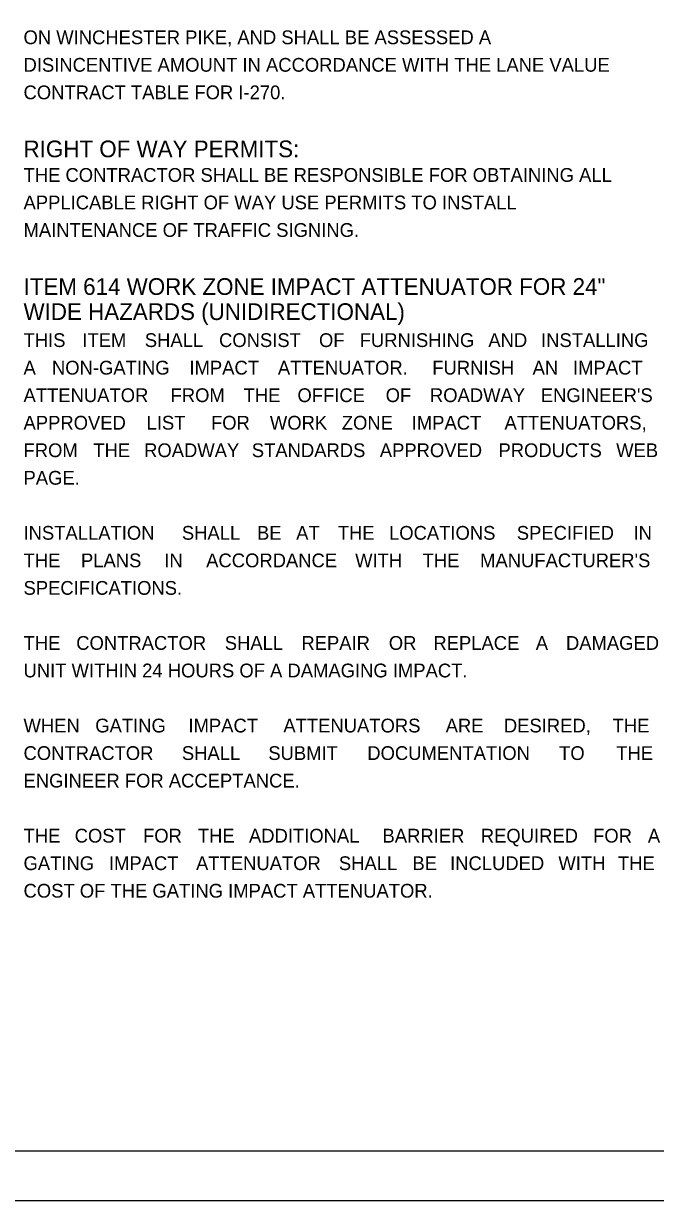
# Model space of a CAD drawing. Extents: x 0 to 34, y 0 to 22.
# Drawn here: x 17.74 to 24.17, y 0 to 11.97 of the extents above; entities that cross this region are included whole.
import ezdxf

# ---------------------------------------------------------------- set-up
doc = ezdxf.new("R2010")
doc.units = 0
for name, color, linetype in [('BD_P_Text', 7, 'Continuous'), ('SH_Border', 7, 'Continuous'), ('SH_Cut_Line', 7, 'Continuous')]:
    doc.layers.add(name, color=color, linetype=linetype)

msp = doc.modelspace()

# ---------------------------------------------------------------- linework, layer by layer
at = {"layer": 'SH_Border'}
msp.add_lwpolyline([(2, 21.5), (33.5, 21.5), (33.5, 0.5), (2, 0.5)], close=True, dxfattribs=at)
at = {"layer": 'SH_Cut_Line'}
msp.add_lwpolyline([(0, 0), (34, 0), (34, 22), (0, 22)], close=True, dxfattribs=at)

# ---------------------------------------------------------------- texts
at = {"layer": 'BD_P_Text'}
for s, height, p in [('ON WINCHESTER PIKE, AND SHALL BE ASSESSED A ', 0.14, (17.74, 11.76)), ('DISINCENTIVE AMOUNT IN ACCORDANCE WITH THE LANE VALUE ', 0.14, (17.74, 11.48)), ('CONTRACT TABLE FOR I-270.', 0.14, (17.74, 11.2)), ('RIGHT OF WAY PERMITS:', 0.17, (17.74, 10.61)), ('THE CONTRACTOR SHALL BE RESPONSIBLE FOR OBTAINING ALL ', 0.14, (17.74, 10.36)), ('APPLICABLE RIGHT OF WAY USE PERMITS TO INSTALL ', 0.14, (17.74, 10.08)), ('MAINTENANCE OF TRAFFIC SIGNING.', 0.14, (17.74, 9.8)), ('ITEM 614 WORK ZONE IMPACT ATTENUATOR FOR 24"', 0.17, (17.74, 9.21)), ('WIDE HAZARDS (UNIDIRECTIONAL)', 0.17, (17.74, 8.955)), ('THIS ', 0.14, (17.74, 8.68)), ('ITEM ', 0.14, (18.338, 8.68)), ('SHALL ', 0.14, (18.973, 8.68)), ('CONSIST ', 0.14, (19.728, 8.68)), ('OF ', 0.14, (20.744, 8.68)), ('FURNISHING ', 0.14, (21.158, 8.68)), ('AND ', 0.14, (22.466, 8.68)), ('INSTALLING ', 0.14, (23.002, 8.68)), ('A ', 0.14, (17.74, 8.4)), ('NON-GATING ', 0.14, (18.029, 8.4)), ('IMPACT ', 0.14, (19.427, 8.4)), ('ATTENUATOR. ', 0.14, (20.326, 8.4)), (' FURNISH ', 0.14, (21.844, 8.4)), ('AN ', 0.14, (22.916, 8.4)), ('IMPACT ', 0.14, (23.327, 8.4)), ('ATTENUATOR ', 0.14, (17.74, 8.12)), ('FROM ', 0.14, (19.235, 8.12)), ('THE ', 0.14, (19.977, 8.12)), ('OFFICE ', 0.14, (20.525, 8.12)), ('OF ', 0.14, (21.422, 8.12)), ('ROADWAY ', 0.14, (21.872, 8.12)), ("ENGINEER'S ", 0.14, (22.999, 8.12)), ('APPROVED ', 0.14, (17.74, 7.84)), ('LIST ', 0.14, (18.991, 7.84)), ('FOR ', 0.14, (19.646, 7.84)), ('WORK ', 0.14, (20.245, 7.84)), ('ZONE ', 0.14, (20.976, 7.84)), ('IMPACT ', 0.14, (21.687, 7.84)), ('ATTENUATORS, ', 0.14, (22.63, 7.84)), ('FROM ', 0.14, (17.74, 7.56)), ('THE ', 0.14, (18.45, 7.56)), ('ROADWAY ', 0.14, (18.966, 7.56)), ('STANDARDS ', 0.14, (20.061, 7.56)), ('APPROVED ', 0.14, (21.362, 7.56)), ('PRODUCTS ', 0.14, (22.569, 7.56)), ('WEB ', 0.14, (23.766, 7.56)), ('PAGE.', 0.14, (17.74, 7.28)), ('INSTALLATION ', 0.14, (17.74, 6.72)), ('SHALL ', 0.14, (19.35, 6.72)), ('BE ', 0.14, (20.114, 6.72)), ('AT ', 0.14, (20.512, 6.72)), ('THE ', 0.14, (20.935, 6.72)), ('LOCATIONS ', 0.14, (21.456, 6.72)), ('SPECIFIED ', 0.14, (22.755, 6.72)), ('IN ', 0.14, (23.942, 6.72)), ('THE ', 0.14, (17.74, 6.44)), ('PLANS ', 0.14, (18.324, 6.44)), ('IN ', 0.14, (19.171, 6.44)), ('ACCORDANCE ', 0.14, (19.597, 6.44)), ('WITH ', 0.14, (21.112, 6.44)), ('THE ', 0.14, (21.798, 6.44)), ("MANUFACTURER'S ", 0.14, (22.382, 6.44)), ('SPECIFICATIONS.', 0.14, (17.74, 6.16)), ('THE ', 0.14, (17.74, 5.6)), ('CONTRACTOR ', 0.14, (18.276, 5.6)), ('SHALL ', 0.14, (19.786, 5.6)), ('REPAIR ', 0.14, (20.565, 5.6)), ('OR ', 0.14, (21.454, 5.6)), ('REPLACE ', 0.14, (21.907, 5.6)), ('A ', 0.14, (22.948, 5.6)), ('DAMAGED ', 0.14, (23.255, 5.6)), ('UNIT WITHIN 24 HOURS OF A DAMAGING IMPACT.', 0.14, (17.74, 5.32)), ('WHEN ', 0.14, (17.74, 4.76)), ('GATING ', 0.14, (18.469, 4.76)), ('IMPACT ', 0.14, (19.417, 4.76)), ('ATTENUATORS ', 0.14, (20.382, 4.76)), ('ARE ', 0.14, (22.032, 4.76)), ('DESIRED, ', 0.14, (22.624, 4.76)), ('THE ', 0.14, (23.729, 4.76)), ('CONTRACTOR ', 0.14, (17.74, 4.48)), ('SHALL ', 0.14, (19.35, 4.48)), ('SUBMIT ', 0.14, (20.229, 4.48)), ('DOCUMENTATION ', 0.14, (21.235, 4.48)), ('TO ', 0.14, (23.185, 4.48)), ('THE ', 0.14, (23.766, 4.48)), ('ENGINEER FOR ACCEPTANCE.', 0.14, (17.74, 4.2)), ('THE ', 0.14, (17.74, 3.64)), ('COST ', 0.14, (18.26, 3.64)), ('FOR ', 0.14, (18.955, 3.64)), ('THE ', 0.14, (19.512, 3.64)), ('ADDITIONAL ', 0.14, (20.032, 3.64)), ('BARRIER ', 0.14, (21.39, 3.64)), ('REQUIRED ', 0.14, (22.389, 3.64)), ('FOR ', 0.14, (23.531, 3.64)), ('A ', 0.14, (24.088, 3.64)), ('GATING ', 0.14, (17.74, 3.36)), ('IMPACT ', 0.14, (18.608, 3.36)), ('ATTENUATOR ', 0.14, (19.494, 3.36)), ('SHALL ', 0.14, (20.946, 3.36)), ('BE ', 0.14, (21.694, 3.36)), ('INCLUDED ', 0.14, (22.077, 3.36)), ('WITH ', 0.14, (23.178, 3.36)), ('THE ', 0.14, (23.784, 3.36)), ('COST OF THE GATING IMPACT ATTENUATOR.', 0.14, (17.74, 3.08))]:
    msp.add_text(s, height=height, dxfattribs=at).set_placement(p)

doc.saveas('drawing.dxf')
